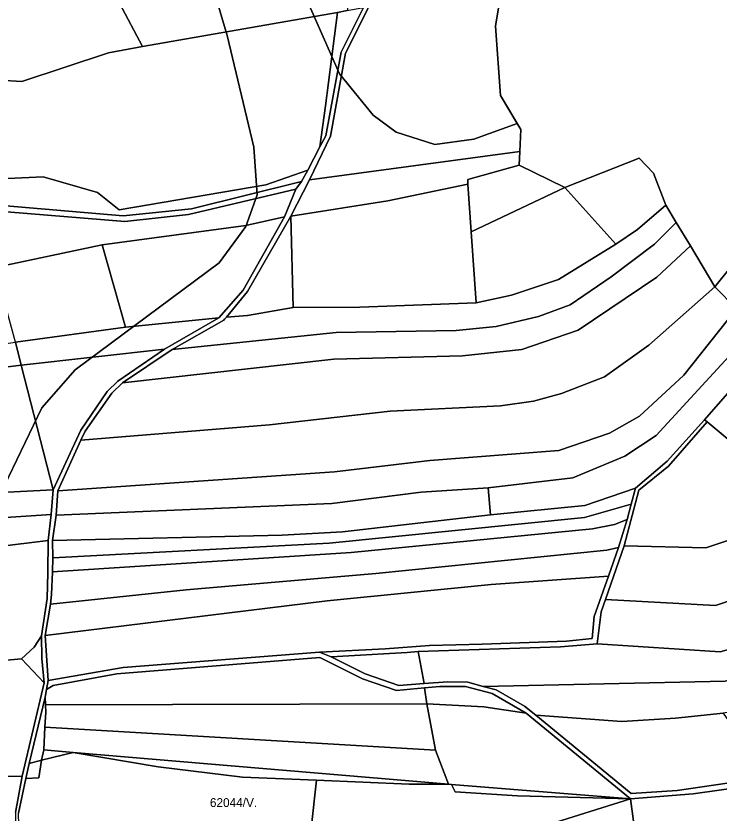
# Model space of a CAD drawing. Extents: x -521261 to -517465, y -1182764 to -1179456.
# Drawn here: x -519071.1 to -518673.2, y -1181572.2 to -1181121.3 of the extents above; entities that cross this region are included whole.
import ezdxf

# ---------------------------------------------------------------- set-up
doc = ezdxf.new("R2010")
doc.units = 0
for name, color, linetype in [('95560013', 7, 'Continuous'), ('95610013', 7, 'Continuous'), ('95620013', 7, 'Continuous'), ('95640013', 7, 'Continuous'), ('95660013', 7, 'Continuous')]:
    doc.layers.add(name, color=color, linetype=linetype)

msp = doc.modelspace()

# ---------------------------------------------------------------- linework, layer by layer
at = {"layer": '95560013'}
for points in [[(-518767.65, -1180900.49), (-518728.61, -1180927.2), (-518771.62, -1181011.43), (-518796.51, -1181107.45), (-518799.71, -1181127.22), (-518796.94, -1181166.4), (-518785.42, -1181185.66), (-518785.86, -1181197.97), (-518905.05, -1181214.06), (-518893.06, -1181189.28), (-518884.51, -1181142.36), (-518872.03, -1181117.32), (-518847.82, -1181058.73), (-518826.41, -1181021.47), (-518801.1, -1180983.45), (-518793.02, -1180965.88)], [(-519025.58, -1181089.49), (-519012.49, -1181114.11), (-518999.4, -1181138.6), (-519018.65, -1181142.26), (-519067.69, -1181158.36), (-519105.92, -1181156.17), (-519117.61, -1181133.12), (-519122.38, -1181115.36), (-519035.38, -1181092.59)], [(-519012.49, -1181114.11), (-518880.14, -1181097.21), (-518883.71, -1181118.34), (-518889.2, -1181119.44), (-518999.4, -1181138.6)], [(-518883.71, -1181118.34), (-518874.47, -1181116.54), (-518887.13, -1181141.85), (-518895.79, -1181189.08), (-518899.2, -1181195.41), (-518895.9, -1181172.24), (-518889.2, -1181119.44)], [(-518889.2, -1181119.44), (-518895.9, -1181172.24), (-518899.2, -1181195.41), (-518905.82, -1181208.56), (-518929.63, -1181216.79), (-519012.63, -1181230.94), (-519025, -1181221.11), (-519055.7, -1181212.28), (-519095.79, -1181214.24), (-519111.04, -1181157.52), (-519105.92, -1181156.17), (-519067.69, -1181158.36), (-519018.65, -1181142.26), (-518999.4, -1181138.6)], [(-518786.29, -1181205.72), (-518815.46, -1181213.78), (-518815.3, -1181216.55), (-518860.62, -1181225.98), (-518915.45, -1181234.59), (-518905.05, -1181214.06), (-518785.86, -1181197.97)], [(-518718.38, -1181201.7), (-518710.23, -1181210.23), (-518703.33, -1181228.32), (-518719.41, -1181242.14), (-518731.66, -1181250.46), (-518760.41, -1181218.29)], [(-518815.46, -1181213.78), (-518786.29, -1181205.72), (-518760.41, -1181218.29), (-518813.54, -1181243.4), (-518815.3, -1181216.55)], [(-519095.79, -1181214.24), (-519055.7, -1181212.28), (-519025, -1181221.11), (-519012.63, -1181230.94), (-518929.63, -1181216.79), (-518905.82, -1181208.56), (-518909.47, -1181214.97), (-518971.76, -1181230.41), (-519010.33, -1181234.48), (-519078.93, -1181228.64), (-519093.4, -1181225.17)], [(-518912.7, -1181219.3), (-518973.45, -1181233.71), (-519009.39, -1181237.66), (-519076.22, -1181232.09), (-519092.61, -1181228.32), (-519093.4, -1181225.17), (-519078.93, -1181228.64), (-519010.33, -1181234.48), (-518971.76, -1181230.41), (-518909.47, -1181214.97)], [(-519092.61, -1181228.32), (-519076.22, -1181232.09), (-519009.39, -1181237.66), (-518973.45, -1181233.71), (-518912.7, -1181219.3), (-518919.05, -1181234.96), (-518941.05, -1181239.81), (-519022.26, -1181250.82), (-519082.97, -1181263.58)], [(-518860.62, -1181225.98), (-518815.3, -1181216.55), (-518813.54, -1181243.4), (-518810.57, -1181283.51), (-518876.39, -1181286.03), (-518914.15, -1181286.21), (-518915.45, -1181234.59)], [(-518760.41, -1181218.29), (-518731.66, -1181250.46), (-518764, -1181270.44), (-518790.65, -1181279.26), (-518810.57, -1181283.51), (-518813.54, -1181243.4)], [(-518703.33, -1181228.32), (-518697.49, -1181238.21), (-518709.77, -1181250.4), (-518734.34, -1181268.92), (-518757.55, -1181284.72), (-518775.36, -1181291.33), (-518799.4, -1181296.89), (-518821.91, -1181299.23), (-518889.87, -1181300.3), (-518982.66, -1181309.99), (-518953.51, -1181293.31), (-518953.14, -1181292.92), (-518952.02, -1181291.79), (-518940.05, -1181290.67), (-518914.15, -1181286.21), (-518876.39, -1181286.03), (-518810.57, -1181283.51), (-518790.65, -1181279.26), (-518764, -1181270.44), (-518731.66, -1181250.46), (-518719.41, -1181242.14)], [(-518941.05, -1181239.81), (-518919.05, -1181234.96), (-518942.44, -1181276.47), (-518956.23, -1181292.13), (-519009.08, -1181297.31), (-519022.26, -1181250.82)], [(-518697.49, -1181238.21), (-518689.45, -1181251.43), (-518708.4, -1181269.14), (-518753.02, -1181299.03), (-518784.76, -1181310.02), (-518818.42, -1181313.57), (-518891.11, -1181315.44), (-519010.82, -1181328.9), (-518982.66, -1181309.99), (-518889.87, -1181300.3), (-518821.91, -1181299.23), (-518799.4, -1181296.89), (-518775.36, -1181291.33), (-518757.55, -1181284.72), (-518734.34, -1181268.92), (-518709.77, -1181250.4)], [(-518939.99, -1181277.22), (-518915.45, -1181234.59), (-518914.15, -1181286.21), (-518940.05, -1181290.67), (-518952.02, -1181291.79)], [(-519082.97, -1181263.58), (-519022.26, -1181250.82), (-519009.08, -1181297.31), (-519071.36, -1181305.91)], [(-518708.4, -1181269.14), (-518689.45, -1181251.43), (-518675.54, -1181274.63), (-518712.97, -1181307.58), (-518738.07, -1181325.54), (-518762.37, -1181334.9), (-518778.15, -1181339.19), (-518796.86, -1181341.76), (-518859.29, -1181344.94), (-518927.65, -1181352.54), (-519034.31, -1181361.29), (-519031.97, -1181356.1), (-519016.82, -1181334.67), (-519010.82, -1181328.9), (-518891.11, -1181315.44), (-518818.42, -1181313.57), (-518784.76, -1181310.02), (-518753.02, -1181299.03)], [(-518675.54, -1181274.63), (-518663.33, -1181287.08), (-518693.19, -1181324.53), (-518718.13, -1181347.7), (-518735.27, -1181357.29), (-518763.95, -1181367.17), (-518836.89, -1181372.83), (-518890.74, -1181379.2), (-519047.36, -1181389.95), (-519034.31, -1181361.29), (-518927.65, -1181352.54), (-518859.29, -1181344.94), (-518796.86, -1181341.76), (-518778.15, -1181339.19), (-518762.37, -1181334.9), (-518738.07, -1181325.54), (-518712.97, -1181307.58)], [(-518637.63, -1181279.33), (-518639.08, -1181284.96), (-518640.69, -1181303.28), (-518681.4, -1181349.69), (-518702.55, -1181373.11), (-518720.57, -1181388.36), (-518749.09, -1181398.29), (-518802.62, -1181403.53), (-518803.83, -1181388.28), (-518755.97, -1181382.48), (-518726.45, -1181370.33), (-518708.77, -1181358.68), (-518652.62, -1181297.59)], [(-518652.62, -1181297.59), (-518708.77, -1181358.68), (-518726.45, -1181370.33), (-518755.97, -1181382.48), (-518803.83, -1181388.28), (-518841.69, -1181390.76), (-518892.4, -1181397.12), (-519048.38, -1181403.77), (-519047.36, -1181389.95), (-518890.74, -1181379.2), (-518836.89, -1181372.83), (-518763.95, -1181367.17), (-518735.27, -1181357.29), (-518718.13, -1181347.7), (-518693.19, -1181324.53), (-518663.33, -1181287.08)], [(-519009.08, -1181297.31), (-518956.23, -1181292.13), (-518987.01, -1181309.77), (-519068.05, -1181318.86), (-519071.36, -1181305.91)], [(-518681.4, -1181349.69), (-518640.69, -1181303.28), (-518647.24, -1181378.13), (-518679.99, -1181350.96)], [(-519068.05, -1181318.86), (-518987.01, -1181309.77), (-519013.51, -1181327.91), (-519019.44, -1181333.83), (-519034.41, -1181355.62), (-519050.06, -1181389.29)], [(-518679.99, -1181350.96), (-518701.77, -1181375.89), (-518718.6, -1181389.5), (-518726.97, -1181421.02), (-518737.42, -1181451.29), (-518739.84, -1181458.33), (-518742.25, -1181476.5), (-518762.88, -1181478.17), (-518843.44, -1181480.79), (-518849.73, -1181481.37), (-518892.62, -1181483.73), (-518899.26, -1181481.13), (-518862.24, -1181479.32), (-518837.06, -1181477.48), (-518807.19, -1181476.72), (-518759.57, -1181474.98), (-518745, -1181473.36), (-518743.86, -1181460.96), (-518735.82, -1181438.22), (-518730.12, -1181422), (-518725.27, -1181406.15), (-518722.95, -1181397.55), (-518720.57, -1181388.36), (-518702.55, -1181373.11), (-518681.4, -1181349.69)], [(-518679.99, -1181350.96), (-518647.24, -1181378.13), (-518649.97, -1181409.3), (-518654.38, -1181413.51), (-518680.65, -1181422.21), (-518726.97, -1181421.02), (-518718.6, -1181389.5), (-518701.77, -1181375.89)], [(-518841.69, -1181390.76), (-518803.83, -1181388.28), (-518802.62, -1181403.53), (-518886.27, -1181413.06), (-518920.51, -1181415.02), (-519050.42, -1181418.01), (-519048.38, -1181403.77), (-518892.4, -1181397.12)], [(-518720.57, -1181388.36), (-518722.95, -1181397.55), (-518749.4, -1181405.01), (-518893.84, -1181419.52), (-519050.24, -1181427.75), (-519050.42, -1181418.01), (-518920.51, -1181415.02), (-518886.27, -1181413.06), (-518802.62, -1181403.53), (-518749.09, -1181398.29)], [(-518749.4, -1181405.01), (-518722.95, -1181397.55), (-518725.27, -1181406.15), (-518732.41, -1181408.96), (-518744.86, -1181411.43), (-518881.33, -1181424.85), (-519050.42, -1181435.73), (-519050.24, -1181427.75), (-518893.84, -1181419.52)], [(-518732.41, -1181408.96), (-518725.27, -1181406.15), (-518730.12, -1181422), (-518736.72, -1181423.44), (-518867.38, -1181436.77), (-518974.81, -1181445.83), (-519051.49, -1181454.04), (-519050.94, -1181448.52), (-519050.42, -1181435.73), (-518881.33, -1181424.85), (-518744.86, -1181411.43)], [(-518654.38, -1181413.51), (-518649.97, -1181409.3), (-518651.9, -1181431.4), (-518652.41, -1181447.08), (-518675.3, -1181454.82), (-518737.42, -1181451.29), (-518726.97, -1181421.02), (-518680.65, -1181422.21)], [(-518736.72, -1181423.44), (-518730.12, -1181422), (-518735.82, -1181438.22), (-518802.2, -1181442.95), (-518894.9, -1181452.15), (-519054.49, -1181471.78), (-519051.49, -1181454.04), (-518974.81, -1181445.83), (-518867.38, -1181436.77)], [(-518802.2, -1181442.95), (-518735.82, -1181438.22), (-518743.86, -1181460.96), (-518745, -1181473.36), (-518759.57, -1181474.98), (-518807.19, -1181476.72), (-518837.06, -1181477.48), (-518862.24, -1181479.32), (-518899.26, -1181481.13), (-519010.47, -1181489.77), (-519052.82, -1181497.18), (-519054.49, -1181471.78), (-518894.9, -1181452.15)], [(-518675.3, -1181454.82), (-518652.41, -1181447.08), (-518653.14, -1181469.35), (-518651.95, -1181475.2), (-518672.49, -1181480.9), (-518742.25, -1181476.5), (-518739.84, -1181458.33), (-518737.42, -1181451.29)], [(-518742.25, -1181476.5), (-518672.49, -1181480.9), (-518651.95, -1181475.2), (-518648.66, -1181491.51), (-518669.81, -1181497.63), (-518806.74, -1181500.53), (-518815.41, -1181498.2), (-518826.73, -1181497.94), (-518840.12, -1181498.94), (-518843.44, -1181480.79), (-518762.88, -1181478.17)], [(-518843.44, -1181480.79), (-518840.12, -1181498.94), (-518854.42, -1181500), (-518873.51, -1181493.39), (-518892.62, -1181483.73), (-518849.73, -1181481.37)], [(-518899.17, -1181484.19), (-518874.92, -1181496.2), (-518855.81, -1181502.88), (-518839.8, -1181501.36), (-518838.65, -1181510.48), (-519054.43, -1181511.02), (-519054.57, -1181506.69), (-519053.71, -1181502.32), (-519049.96, -1181500.05), (-519014.04, -1181493.39)], [(-518648.66, -1181491.51), (-518648.14, -1181494.08), (-518644.42, -1181509.49), (-518655.76, -1181513.23), (-518670.85, -1181515.74), (-518697.81, -1181518.58), (-518728.22, -1181520.3), (-518776.82, -1181516.87), (-518783.32, -1181511.62), (-518799.29, -1181502.53), (-518806.74, -1181500.53), (-518669.81, -1181497.63)], [(-518816.62, -1181500.66), (-518801.65, -1181504.53), (-518782.33, -1181515.59), (-518806.23, -1181512.09), (-518838.65, -1181510.48), (-518839.8, -1181501.36), (-518831.14, -1181500.54)], [(-519054.43, -1181511.02), (-519054.23, -1181515.16), (-519054.72, -1181523.54), (-519055.27, -1181536.42), (-519056.63, -1181542.34), (-519063.59, -1181544.04), (-519054.57, -1181506.69)], [(-518838.65, -1181510.48), (-518833.74, -1181536.57), (-519054.72, -1181523.54), (-519054.23, -1181515.16), (-519054.43, -1181511.02)], [(-518838.65, -1181510.48), (-518806.23, -1181512.09), (-518782.33, -1181515.59), (-518723.26, -1181564.13), (-518824.61, -1181555.94), (-518826.34, -1181555.79), (-518833.74, -1181536.57)], [(-518697.81, -1181518.58), (-518670.85, -1181515.74), (-518661.41, -1181529.26), (-518640.29, -1181551.02), (-518696.97, -1181559.36), (-518722.86, -1181561.13), (-518776.82, -1181516.87), (-518728.22, -1181520.3)], [(-519055.27, -1181536.42), (-519054.72, -1181523.54), (-518833.74, -1181536.57), (-518826.34, -1181555.79), (-519038.76, -1181537.95)], [(-519038.76, -1181537.95), (-519056.63, -1181542.34), (-519055.27, -1181536.42)]]:
    msp.add_lwpolyline(points, close=True, dxfattribs=at)
msp.add_lwpolyline([(-518659.72, -1181557.32), (-518687.87, -1181561.31), (-518723.26, -1181564.13), (-518782.33, -1181515.59), (-518801.65, -1181504.53), (-518816.62, -1181500.66), (-518831.14, -1181500.54), (-518839.8, -1181501.36), (-518855.81, -1181502.88), (-518874.92, -1181496.2), (-518899.17, -1181484.19), (-519014.04, -1181493.39), (-519049.96, -1181500.05), (-519053.71, -1181502.32), (-519052.82, -1181497.18), (-519010.47, -1181489.77), (-518899.26, -1181481.13), (-518892.62, -1181483.73), (-518873.51, -1181493.39), (-518854.42, -1181500), (-518840.12, -1181498.94), (-518826.73, -1181497.94), (-518815.41, -1181498.2), (-518806.74, -1181500.53), (-518799.29, -1181502.53), (-518783.32, -1181511.62), (-518776.82, -1181516.87), (-518722.86, -1181561.13), (-518696.97, -1181559.36), (-518640.29, -1181551.02)], dxfattribs=at)
at = {"layer": '95610013'}
for points in [[(-519071.36, -1181305.91), (-519068.05, -1181318.86), (-519092.32, -1181321.85), (-519111.46, -1181324.1), (-519157.34, -1181329.91), (-519161.94, -1181318.99)], [(-519068.05, -1181318.86), (-519050.06, -1181389.29), (-519083.5, -1181391.08), (-519092.32, -1181321.85)], [(-519083.5, -1181391.08), (-519050.06, -1181389.29), (-519051.15, -1181403.27), (-519076.76, -1181404.95), (-519091.09, -1181406.42), (-519124.01, -1181411.59), (-519198.34, -1181431.62), (-519192.44, -1181414.4), (-519185.65, -1181412.62), (-519147.74, -1181401.84), (-519123.65, -1181396.18), (-519104.42, -1181393.61)], [(-519051.15, -1181403.27), (-519052.84, -1181418.09), (-519089.94, -1181422.52), (-519126.23, -1181428.98), (-519137.58, -1181431.41), (-519147.88, -1181433.75), (-519160.64, -1181436.45), (-519196.76, -1181446.54), (-519198.34, -1181431.62), (-519124.01, -1181411.59), (-519091.09, -1181406.42), (-519076.76, -1181404.95)], [(-519052.84, -1181418.09), (-519053.08, -1181436.33), (-519053.47, -1181450.82), (-519056.63, -1181471.96), (-519060.85, -1181478.3), (-519067.87, -1181484.88), (-519109.28, -1181488.69), (-519126.23, -1181428.98), (-519089.94, -1181422.52)], [(-519056.63, -1181471.96), (-519056.42, -1181484.76), (-519055.08, -1181498.43), (-519067.87, -1181484.88), (-519060.85, -1181478.3)], [(-519109.28, -1181488.69), (-519067.87, -1181484.88), (-519055.08, -1181498.43), (-519067.58, -1181551.39), (-519142.99, -1181552.52), (-519169.67, -1181557.22), (-519178.29, -1181530.95), (-519184.7, -1181511.28), (-519190.01, -1181495.32), (-519182.71, -1181494.43), (-519132.38, -1181490.65), (-519121.15, -1181489.64)], [(-519038.76, -1181537.95), (-518990.6, -1181545.96), (-518942.86, -1181551.77), (-518901.08, -1181553.47), (-518907.13, -1181608.19), (-518904.84, -1181620.97), (-518904.97, -1181624.36), (-519069.21, -1181585.42), (-519069.58, -1181572.29), (-519065.53, -1181552.63), (-519058.18, -1181552.18), (-519056.63, -1181542.34)], [(-518990.6, -1181545.96), (-519038.76, -1181537.95), (-518826.34, -1181555.79), (-518848.55, -1181555.76), (-518901.08, -1181553.47), (-518942.86, -1181551.77)], [(-519056.63, -1181542.34), (-519058.18, -1181552.18), (-519065.53, -1181552.63), (-519063.59, -1181544.04)], [(-519142.99, -1181552.52), (-519067.58, -1181551.39), (-519071.41, -1181571.77), (-519071.31, -1181597.58), (-519067.28, -1181625.11), (-519068.11, -1181638.62), (-519072.39, -1181647.92), (-519089.22, -1181656.12), (-519097.9, -1181642.79), (-519108.09, -1181625.41), (-519116.8, -1181607.41)], [(-518901.08, -1181553.47), (-518848.55, -1181555.76), (-518826.34, -1181555.79), (-518824.61, -1181555.94), (-518822.58, -1181560.08), (-518787.18, -1181562.36), (-518723.26, -1181564.13), (-518904.84, -1181620.97), (-518907.13, -1181608.19)], [(-518636.93, -1181553.72), (-518618.32, -1181572.55), (-518661.16, -1181579.52), (-518719.19, -1181593.81), (-518719.53, -1181592.27), (-518723.26, -1181564.13), (-518687.87, -1181561.31), (-518659.72, -1181557.32)], [(-518824.61, -1181555.94), (-518723.26, -1181564.13), (-518787.18, -1181562.36), (-518822.58, -1181560.08)], [(-518723.26, -1181564.13), (-518719.53, -1181592.27), (-518738.67, -1181594.7), (-518762.01, -1181601.41), (-518783.16, -1181606.24), (-518808.96, -1181616.3), (-518836.82, -1181632.23), (-518900.63, -1181671.03), (-518904.97, -1181624.36), (-518904.84, -1181620.97)]]:
    msp.add_lwpolyline(points, close=True, dxfattribs=at)
at = {"layer": '95620013'}
msp.add_lwpolyline([(-518572.75, -1181111.95), (-518562.06, -1181128.41), (-518566.98, -1181148.39), (-518576.06, -1181170.33), (-518621.98, -1181238.21), (-518623.17, -1181237.54), (-518636.38, -1181225.73), (-518675.54, -1181274.63), (-518689.45, -1181251.43), (-518697.49, -1181238.21), (-518703.33, -1181228.32), (-518710.23, -1181210.23), (-518718.38, -1181201.7), (-518760.41, -1181218.29), (-518786.29, -1181205.72), (-518785.86, -1181197.97), (-518785.42, -1181185.66), (-518796.94, -1181166.4), (-518799.71, -1181127.22), (-518796.51, -1181107.45)], dxfattribs=at)
msp.add_lwpolyline([(-518623.17, -1181237.54), (-518663.33, -1181287.08), (-518675.54, -1181274.63), (-518636.38, -1181225.73)], close=True, dxfattribs=at)
at = {"layer": '95640013'}
for points in [[(-519071.41, -1181571.77), (-519067.58, -1181551.39), (-519055.08, -1181498.43), (-519056.42, -1181484.76), (-519056.63, -1181471.96), (-519053.47, -1181450.82), (-519053.08, -1181436.33), (-519052.84, -1181418.09), (-519051.15, -1181403.27), (-519050.06, -1181389.29), (-519034.41, -1181355.62), (-519019.44, -1181333.83), (-519013.51, -1181327.91), (-518987.01, -1181309.77), (-518956.23, -1181292.13), (-518942.44, -1181276.47), (-518919.05, -1181234.96), (-518912.7, -1181219.3), (-518909.47, -1181214.97), (-518905.82, -1181208.56), (-518899.2, -1181195.41), (-518895.79, -1181189.08), (-518887.13, -1181141.85), (-518874.47, -1181116.54)], [(-518872.03, -1181117.32), (-518884.51, -1181142.36), (-518893.06, -1181189.28), (-518905.05, -1181214.06), (-518915.45, -1181234.59), (-518939.99, -1181277.22), (-518952.02, -1181291.79), (-518953.14, -1181292.92), (-518953.51, -1181293.31), (-518982.66, -1181309.99), (-519010.82, -1181328.9), (-519016.82, -1181334.67), (-519031.97, -1181356.1), (-519034.31, -1181361.29), (-519047.36, -1181389.95), (-519048.38, -1181403.77), (-519050.42, -1181418.01), (-519050.24, -1181427.75), (-519050.42, -1181435.73), (-519050.94, -1181448.52), (-519051.49, -1181454.04), (-519054.49, -1181471.78), (-519052.82, -1181497.18), (-519053.71, -1181502.32), (-519054.57, -1181506.69), (-519063.59, -1181544.04), (-519065.53, -1181552.63), (-519069.58, -1181572.29)]]:
    msp.add_lwpolyline(points, dxfattribs=at)
at = {"layer": '95660013'}
for points in [[(-519080, -1181392), (-519056.5, -1181343), (-519037.5, -1181321.5), (-518956, -1181261), (-518941, -1181240.5), (-518934.5, -1181222.5), (-518936.5, -1181195.5), (-518951.5, -1181132.5), (-518983.5, -1181024.5)], [(-518983.5, -1181024.5), (-518951.5, -1181132.5), (-518936.5, -1181195.5), (-518934.5, -1181222.5), (-518941, -1181240.5), (-518956, -1181261), (-519037.5, -1181321.5), (-519056.5, -1181343), (-519080, -1181392)], [(-518796.51, -1181107.45), (-518799.71, -1181127.22), (-518796.94, -1181166.4), (-518787.48, -1181182.22), (-518812, -1181191), (-518834, -1181194), (-518856, -1181187), (-518869, -1181177.5), (-518888, -1181154), (-518906.5, -1181112)], [(-518663.33, -1181287.08), (-518675.54, -1181274.63), (-518689.45, -1181251.43), (-518697.49, -1181238.21), (-518703.33, -1181228.32), (-518710.23, -1181210.23), (-518718.38, -1181201.7), (-518760.41, -1181218.29), (-518786.29, -1181205.72), (-518785.86, -1181197.97), (-518785.42, -1181185.66), (-518787.48, -1181182.22), (-518796.94, -1181166.4), (-518799.71, -1181127.22), (-518796.51, -1181107.45)], [(-518906.5, -1181112), (-518888, -1181154), (-518869, -1181177.5), (-518856, -1181187), (-518834, -1181194), (-518812, -1181191), (-518787.48, -1181182.22), (-518785.42, -1181185.66), (-518785.86, -1181197.97), (-518786.29, -1181205.72), (-518760.41, -1181218.29), (-518718.38, -1181201.7), (-518710.23, -1181210.23), (-518703.33, -1181228.32), (-518697.49, -1181238.21), (-518689.45, -1181251.43), (-518675.54, -1181274.63), (-518663.33, -1181287.08)]]:
    msp.add_lwpolyline(points, dxfattribs=at)

# ---------------------------------------------------------------- texts
msp.add_text('62044/V.', height=5, rotation=360, dxfattribs=at).set_placement((-518961.34, -1181568.73))

doc.saveas('drawing.dxf')
